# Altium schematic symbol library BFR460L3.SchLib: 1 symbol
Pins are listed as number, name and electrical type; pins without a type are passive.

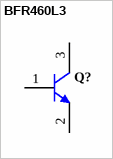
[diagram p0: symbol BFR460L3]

## BFR460L3
designator Q?
NPN Silicon RF Transistor, 4.5 V VCEO, 50 mA IC, 16 dB Gmax, TSLP-3-1, Green; Manufacturer: Infineon; PartNumber: BFR460L3; Gmax (typ): 16 dB; Green: yes; Group: For Modules in TSLP-package; IC (max): 50 mA; NFmin (typ): 1.1 dB; Ptot (max): 200 mW; VCEO (max): 4.5 V
footprint INF-TSLP-3-1_V (TSLP, 3-Leads, Body 0.6x1 mm)
pins: 1 B, 2 E, 3 C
